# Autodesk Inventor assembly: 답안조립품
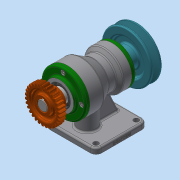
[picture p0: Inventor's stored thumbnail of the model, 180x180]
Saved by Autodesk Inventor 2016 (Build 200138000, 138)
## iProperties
Created: 2019-01
Part Number: 답안조립품
Document SubType Name: Assembly
Designer: 2-PC10
Author: 2-PC10
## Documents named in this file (15)
- C:\Users\2-PC10\Desktop\490108V1010\답안조립품.iam
- C:\Users\2-PC10\Desktop\490108V1010\본체.ipt
- C:\Users\2-PC10\Desktop\490108V1010\베어링 6203.ipt
- C:\Users\2-PC10\Desktop\490108V1010\베어링 6205.ipt
- C:\Users\2-PC10\Desktop\490108V1010\축.ipt
- C:\Users\2-PC10\Desktop\490108V1010\앞커버.ipt
- C:\Users\2-PC10\Desktop\490108V1010\뒤커버.ipt
- C:\Users\2-PC10\Desktop\490108V1010\오일 실 25 38 8.ipt
- C:\Users\2-PC10\Desktop\490108V1010\오일 실 17 30 8.ipt
- C:\Users\2-PC10\Desktop\490108V1010\볼트 M4.ipt
- C:\Users\2-PC10\Desktop\490108V1010\키 6 x 6 x 18.ipt
- C:\Users\2-PC10\Desktop\490108V1010\키 5 x 5 x 20.ipt
- C:\Users\2-PC10\Desktop\490108V1010\스퍼기어.ipt
- C:\Users\2-PC10\Desktop\490108V1010\V-벨트풀리.ipt
- C:\Users\2-PC10\Desktop\490108V1010\멈춤나사 M3.ipt
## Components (1 placed, 1 different names)
1. V-벨트풀리:1 — 플러쉬:2
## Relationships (1: Flush 1)
- 플러쉬:2 [Flush]: V-벨트풀리:1
